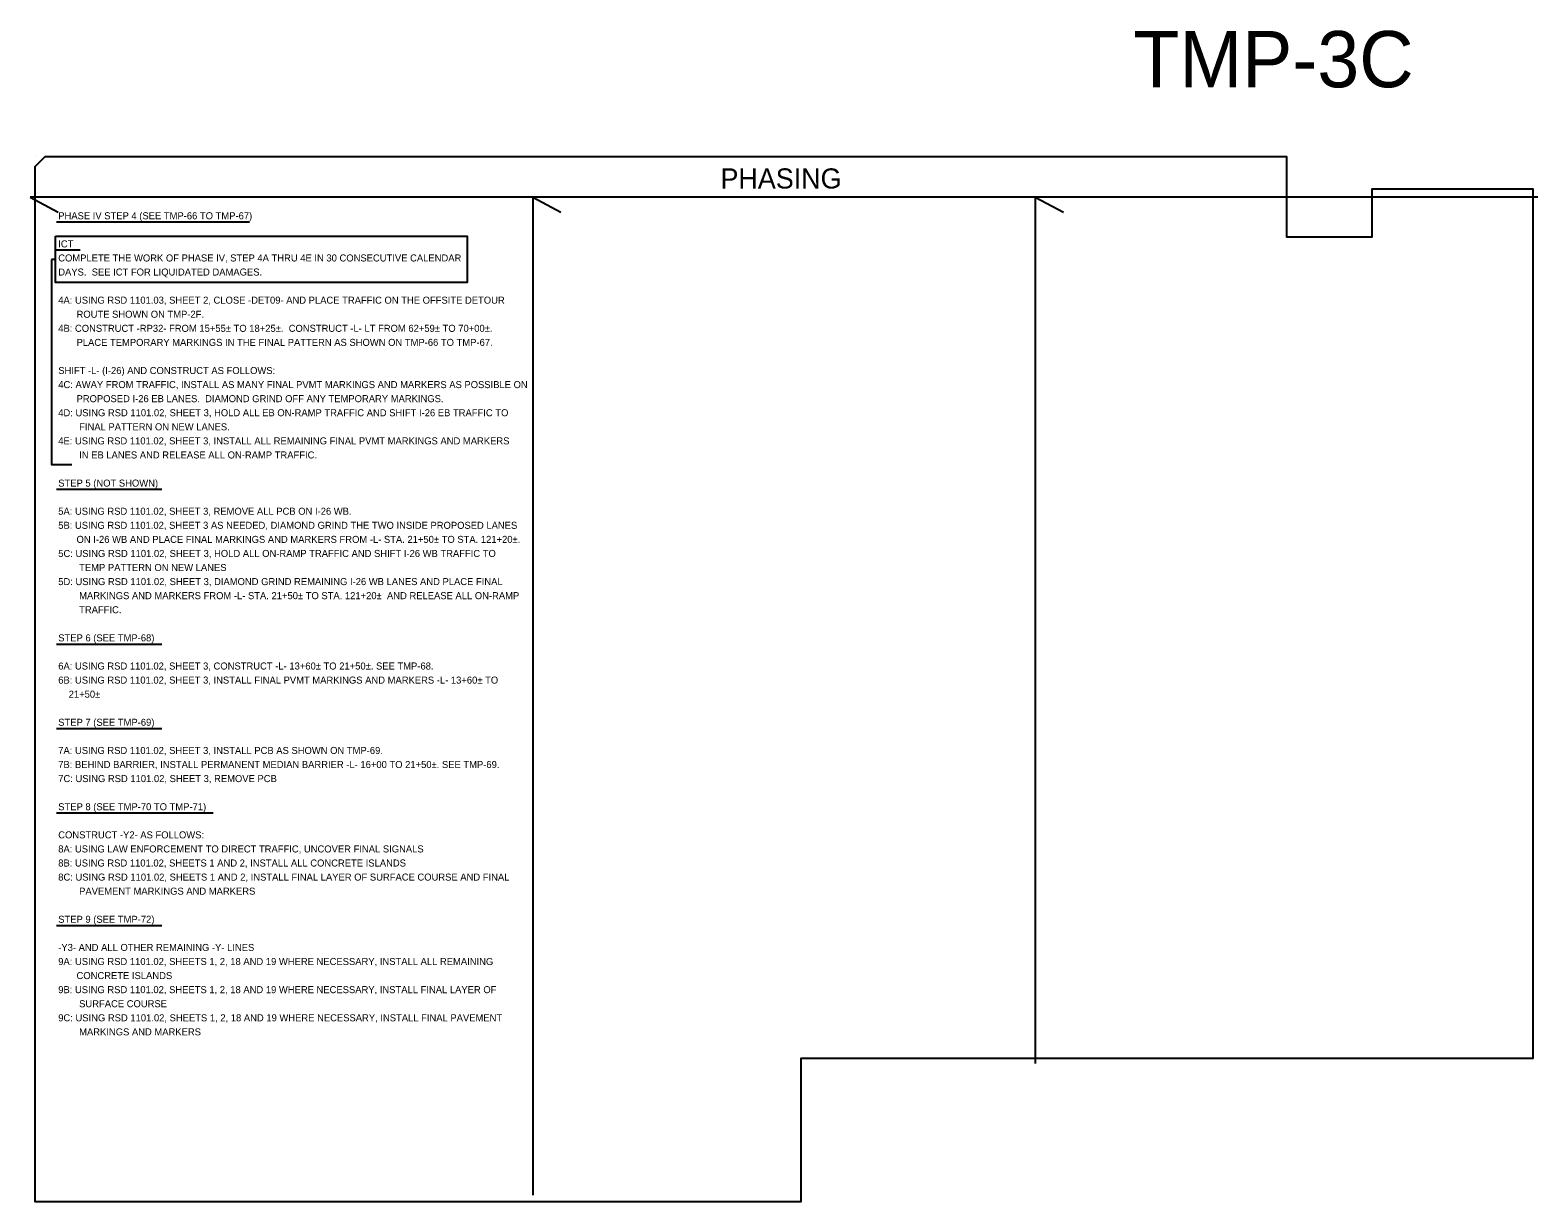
# Model space of a CAD drawing. Extents: x 2483905 to 2494512, y 366160 to 372330.
# Drawn here: x 2493012 to 2494512, y 370218 to 371384 of the extents above; entities that cross this region are included whole.
import ezdxf

# ---------------------------------------------------------------- set-up
doc = ezdxf.new("R2010")
doc.units = 0
for name, color, linetype in [('Prop Mkg Solid White Edge Line', 7, 'Continuous'), ('Scratch_Level_3', 7, 'Continuous'), ('Scratch_Level_6', 7, 'Continuous'), ('TC SHEET BORDER LINE THIN', 7, 'Continuous'), ('TC SHEET LAYOUT SHAPE', 7, 'Continuous'), ('TC SHEET TEXT', 7, 'Continuous')]:
    doc.layers.add(name, color=color, linetype=linetype)

msp = doc.modelspace()

# ---------------------------------------------------------------- linework, layer by layer
at = {"layer": 'Prop Mkg Solid White Edge Line'}
for p, q in [((2493036.7, 371155.9), (2493032.7, 371155.9)), ((2493032.2, 370978.3), (2493032.2, 370978.3))]:
    msp.add_line(p, q, dxfattribs=at)
msp.add_lwpolyline([(2493036.7, 371179), (2493446.3, 371179), (2493446.3, 371132.9), (2493036.7, 371132.9)], close=True, dxfattribs=at)
msp.add_lwpolyline([(2493032.7, 371155.9), (2493032.7, 370952), (2493053.1, 370952)], dxfattribs=at)
at = {"layer": 'Scratch_Level_3'}
msp.add_line((2493016.6, 371258.3), (2493016.6, 371258.3), dxfattribs=at)
at = {"layer": 'Scratch_Level_6'}
for p, q in [((2493011.6, 371218), (2493039.5, 371202.9)), ((2493511.6, 371218), (2493539.5, 371202.9)), ((2494011.6, 371218), (2494039.5, 371202.9))]:
    msp.add_line(p, q, dxfattribs=at)
at = {"layer": 'TC SHEET BORDER LINE THIN'}
for p, q in [((2494511.6, 371218), (2493011.6, 371218)), ((2493511.6, 371218), (2493511.6, 370224.8)), ((2494011.6, 371218), (2494011.6, 370355.9)), ((2493037.8, 371193.3), (2493229.8, 371193.3)), ((2493037.7, 371165.5), (2493061.3, 371165.5)), ((2493037.8, 370927.3), (2493142.6, 370927.3)), ((2493037.8, 370773.3), (2493142.6, 370773.3)), ((2493037.8, 370689.3), (2493142.6, 370689.3)), ((2493037.8, 370605.3), (2493193.5, 370605.3)), ((2493037.8, 370493.3), (2493142.6, 370493.3))]:
    msp.add_line(p, q, dxfattribs=at)
at = {"layer": 'TC SHEET LAYOUT SHAPE'}
msp.add_lwpolyline([(2493016.6, 370666.8), (2493016.6, 370976.2), (2493016.6, 371248.3), (2493026.6, 371258.3), (2493469.6, 371258.3), (2493940.6, 371258.3), (2494261.6, 371258.3), (2494261.6, 371178.3), (2494346.6, 371178.3), (2494346.6, 371226.3), (2494506.6, 371226.3), (2494506.6, 370891.3), (2494506.6, 370612.1), (2494506.6, 370360.8), (2493778.4, 370360.8), (2493778.4, 370218.3), (2493608.9, 370218.3), (2493256.1, 370218.3), (2493016.6, 370218.3)], close=True, dxfattribs=at)

# ---------------------------------------------------------------- texts
at = {"layer": 'TC SHEET BORDER LINE THIN'}
for s, p in [('PHASE IV STEP 4 (SEE TMP-66 TO TMP-67)', (2493039.5, 371195.9)), ('COMPLETE THE WORK OF PHASE IV, STEP 4A THRU 4E IN 30 CONSECUTIVE CALENDAR', (2493039.5, 371153.9)), ('ICT', (2493039.5, 371167.9)), ('DAYS.  SEE ICT FOR LIQUIDATED DAMAGES.', (2493039.5, 371139.9)), ('4A: USING RSD 1101.03, SHEET 2, CLOSE -DET09- AND PLACE TRAFFIC ON THE OFFSITE DETOUR', (2493039.5, 371111.9)), ('       ROUTE SHOWN ON TMP-2F.', (2493039.5, 371097.9)), ('4B: CONSTRUCT -RP32- FROM 15+55± TO 18+25±.  CONSTRUCT -L- LT FROM 62+59± TO 70+00±.', (2493039.5, 371083.9)), ('       PLACE TEMPORARY MARKINGS IN THE FINAL PATTERN AS SHOWN ON TMP-66 TO TMP-67.', (2493039.5, 371069.9)), ('SHIFT -L- (I-26) AND CONSTRUCT AS FOLLOWS:', (2493039.5, 371041.9)), ('4C: AWAY FROM TRAFFIC, INSTALL AS MANY FINAL PVMT MARKINGS AND MARKERS AS POSSIBLE ON', (2493039.5, 371027.9)), ('       PROPOSED I-26 EB LANES.  DIAMOND GRIND OFF ANY TEMPORARY MARKINGS.', (2493039.5, 371013.9)), ('4D: USING RSD 1101.02, SHEET 3, HOLD ALL EB ON-RAMP TRAFFIC AND SHIFT I-26 EB TRAFFIC TO', (2493039.5, 370999.9)), ('        FINAL PATTERN ON NEW LANES.', (2493039.5, 370985.9)), ('4E: USING RSD 1101.02, SHEET 3, INSTALL ALL REMAINING FINAL PVMT MARKINGS AND MARKERS', (2493039.5, 370971.9)), ('        IN EB LANES AND RELEASE ALL ON-RAMP TRAFFIC.', (2493039.5, 370957.9)), ('STEP 5 (NOT SHOWN)', (2493039.5, 370929.9)), ('5A: USING RSD 1101.02, SHEET 3, REMOVE ALL PCB ON I-26 WB.', (2493039.5, 370901.9)), ('5B: USING RSD 1101.02, SHEET 3 AS NEEDED, DIAMOND GRIND THE TWO INSIDE PROPOSED LANES', (2493039.5, 370887.9)), ('       ON I-26 WB AND PLACE FINAL MARKINGS AND MARKERS FROM -L- STA. 21+50± TO STA. 121+20±.', (2493039.5, 370873.9)), ('5C: USING RSD 1101.02, SHEET 3, HOLD ALL ON-RAMP TRAFFIC AND SHIFT I-26 WB TRAFFIC TO', (2493039.5, 370859.9)), ('        TEMP PATTERN ON NEW LANES', (2493039.5, 370845.9)), ('5D: USING RSD 1101.02, SHEET 3, DIAMOND GRIND REMAINING I-26 WB LANES AND PLACE FINAL', (2493039.5, 370831.9)), ('        MARKINGS AND MARKERS FROM -L- STA. 21+50± TO STA. 121+20±  AND RELEASE ALL ON-RAMP ', (2493039.5, 370817.9)), ('        TRAFFIC.', (2493039.5, 370803.9)), ('STEP 6 (SEE TMP-68)', (2493039.5, 370775.9)), ('6A: USING RSD 1101.02, SHEET 3, CONSTRUCT -L- 13+60± TO 21+50±. SEE TMP-68.', (2493039.5, 370747.9)), ('6B: USING RSD 1101.02, SHEET 3, INSTALL FINAL PVMT MARKINGS AND MARKERS -L- 13+60± TO', (2493039.5, 370733.9)), ('    21+50±', (2493039.5, 370719.9)), ('STEP 7 (SEE TMP-69)', (2493039.5, 370691.9)), ('7A: USING RSD 1101.02, SHEET 3, INSTALL PCB AS SHOWN ON TMP-69.', (2493039.5, 370663.9)), ('7B: BEHIND BARRIER, INSTALL PERMANENT MEDIAN BARRIER -L- 16+00 TO 21+50±. SEE TMP-69.', (2493039.5, 370649.9)), ('7C: USING RSD 1101.02, SHEET 3, REMOVE PCB', (2493039.5, 370635.9)), ('STEP 8 (SEE TMP-70 TO TMP-71)', (2493039.5, 370607.9)), ('CONSTRUCT -Y2- AS FOLLOWS:', (2493039.5, 370579.9)), ('8A: USING LAW ENFORCEMENT TO DIRECT TRAFFIC, UNCOVER FINAL SIGNALS', (2493039.5, 370565.9)), ('8B: USING RSD 1101.02, SHEETS 1 AND 2, INSTALL ALL CONCRETE ISLANDS', (2493039.5, 370551.9)), ('8C: USING RSD 1101.02, SHEETS 1 AND 2, INSTALL FINAL LAYER OF SURFACE COURSE AND FINAL', (2493039.5, 370537.9)), ('        PAVEMENT MARKINGS AND MARKERS', (2493039.5, 370523.9)), ('STEP 9 (SEE TMP-72)', (2493039.5, 370495.9)), ('-Y3- AND ALL OTHER REMAINING -Y- LINES', (2493039.5, 370467.9)), ('9A: USING RSD 1101.02, SHEETS 1, 2, 18 AND 19 WHERE NECESSARY, INSTALL ALL REMAINING', (2493039.5, 370453.9)), ('       CONCRETE ISLANDS', (2493039.5, 370439.9)), ('9B: USING RSD 1101.02, SHEETS 1, 2, 18 AND 19 WHERE NECESSARY, INSTALL FINAL LAYER OF', (2493039.5, 370425.9)), ('        SURFACE COURSE', (2493039.5, 370411.9)), ('9C: USING RSD 1101.02, SHEETS 1, 2, 18 AND 19 WHERE NECESSARY, INSTALL FINAL PAVEMENT', (2493039.5, 370397.9)), ('        MARKINGS AND MARKERS', (2493039.5, 370383.9))]:
    msp.add_text(s, height=7, dxfattribs=at).set_placement(p)
at = {"layer": 'TC SHEET LAYOUT SHAPE'}
msp.add_text('TMP-3C', height=56, rotation=0.0001, dxfattribs=at).set_placement((2494109.2, 371327.2))
at = {"layer": 'TC SHEET TEXT'}
msp.add_text('PHASING', height=20, rotation=359.9999, dxfattribs=at).set_placement((2493698.4, 371226.5))

doc.saveas('drawing.dxf')
